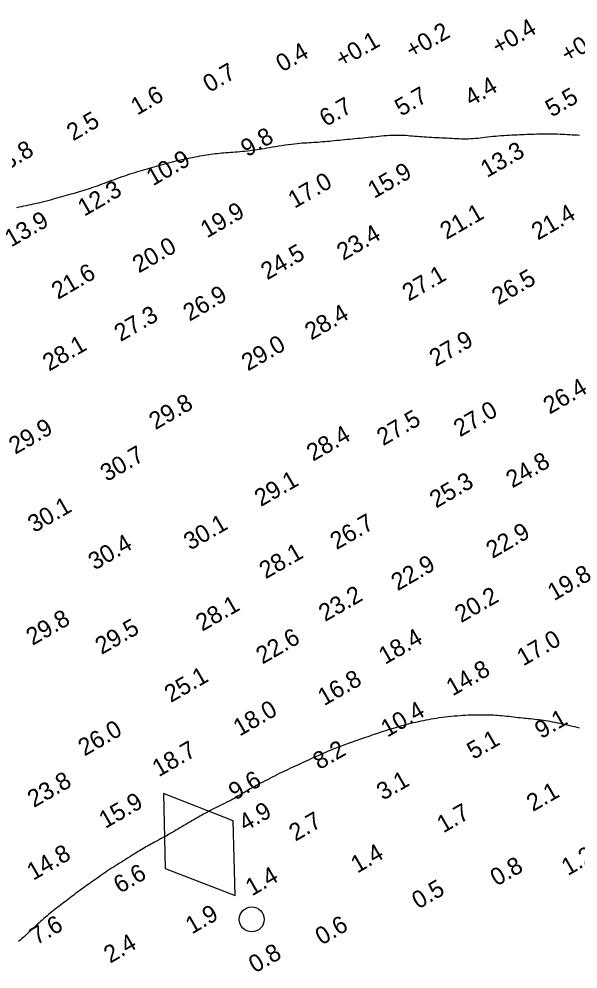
# Model space of a CAD drawing. Extents: x 3024098 to 3056816, y 418252 to 509144.
# Drawn here: x 3027600.4 to 3027761.7, y 427846.4 to 428120.8 of the extents above; entities that cross this region are included whole.
import ezdxf

# ---------------------------------------------------------------- set-up
doc = ezdxf.new("R2010")
doc.units = 0
for name, color, linetype in [('V-CHAN-CONT-EL10', 7, 'Continuous'), ('V-CHAN-NAID', 7, 'Continuous'), ('V-TOPO-SOUN-0911', 7, 'Continuous')]:
    doc.layers.add(name, color=color, linetype=linetype)

msp = doc.modelspace()

# ---------------------------------------------------------------- linework, layer by layer
at = {"layer": 'V-CHAN-CONT-EL10'}
for points in [[(3027599.77, 428066.31), (3027600.45, 428066.47), (3027601.12, 428066.63), (3027601.8, 428066.78), (3027602.49, 428066.93), (3027603.18, 428067.08), (3027603.88, 428067.23), (3027604.59, 428067.39), (3027605.31, 428067.55), (3027606.04, 428067.71), (3027606.79, 428067.89), (3027607.55, 428068.08), (3027608.31, 428068.27), (3027609.08, 428068.47), (3027609.84, 428068.67), (3027610.59, 428068.88), (3027611.33, 428069.08), (3027612.05, 428069.28), (3027612.75, 428069.47), (3027613.43, 428069.67), (3027614.09, 428069.85), (3027614.74, 428070.04), (3027615.38, 428070.23), (3027616.01, 428070.41), (3027616.63, 428070.6), (3027617.26, 428070.78), (3027617.88, 428070.96), (3027618.51, 428071.15), (3027619.14, 428071.34), (3027619.77, 428071.54), (3027620.4, 428071.74), (3027621.04, 428071.95), (3027621.69, 428072.16), (3027622.35, 428072.39), (3027623.01, 428072.62), (3027623.68, 428072.87), (3027624.36, 428073.12), (3027625.04, 428073.38), (3027625.74, 428073.65), (3027626.45, 428073.92), (3027627.16, 428074.19), (3027627.89, 428074.46), (3027628.63, 428074.73), (3027629.38, 428074.99), (3027630.13, 428075.26), (3027630.88, 428075.51), (3027631.64, 428075.77), (3027632.39, 428076.01), (3027633.13, 428076.25), (3027633.86, 428076.48), (3027634.58, 428076.7), (3027635.29, 428076.91), (3027635.98, 428077.11), (3027636.67, 428077.3), (3027637.36, 428077.49), (3027638.04, 428077.68), (3027638.71, 428077.87), (3027639.39, 428078.06), (3027640.06, 428078.25), (3027640.74, 428078.44), (3027641.43, 428078.63), (3027642.12, 428078.82), (3027642.82, 428079.02), (3027643.53, 428079.21), (3027644.26, 428079.4), (3027645.01, 428079.59), (3027645.77, 428079.78), (3027646.55, 428079.96), (3027647.33, 428080.15), (3027648.12, 428080.32), (3027648.9, 428080.49), (3027649.68, 428080.66), (3027650.44, 428080.81), (3027651.17, 428080.96), (3027651.88, 428081.1), (3027652.57, 428081.22), (3027653.24, 428081.34), (3027653.89, 428081.45), (3027654.52, 428081.55), (3027655.14, 428081.65), (3027655.76, 428081.73), (3027656.36, 428081.81), (3027656.97, 428081.88), (3027657.58, 428081.95), (3027658.19, 428082.01), (3027658.8, 428082.07), (3027659.42, 428082.12), (3027660.06, 428082.17), (3027660.7, 428082.23), (3027661.36, 428082.28), (3027662.04, 428082.33), (3027662.73, 428082.38), (3027663.44, 428082.43), (3027664.14, 428082.49), (3027664.85, 428082.55), (3027665.56, 428082.62), (3027666.26, 428082.69), (3027666.95, 428082.77), (3027667.63, 428082.85), (3027668.3, 428082.95), (3027668.97, 428083.05), (3027669.65, 428083.16), (3027670.35, 428083.28), (3027671.08, 428083.4), (3027671.84, 428083.53), (3027672.64, 428083.67), (3027673.5, 428083.82), (3027674.39, 428083.97), (3027675.31, 428084.12), (3027676.24, 428084.27), (3027677.17, 428084.41), (3027678.08, 428084.54), (3027678.97, 428084.66), (3027679.82, 428084.76), (3027680.62, 428084.84), (3027681.37, 428084.91), (3027682.08, 428084.97), (3027682.77, 428085.01), (3027683.43, 428085.05), (3027684.07, 428085.08), (3027684.7, 428085.12), (3027685.33, 428085.15), (3027685.97, 428085.19), (3027686.61, 428085.24), (3027687.26, 428085.29), (3027687.92, 428085.34), (3027688.58, 428085.4), (3027689.26, 428085.46), (3027689.95, 428085.53), (3027690.65, 428085.59), (3027691.36, 428085.66), (3027692.08, 428085.73), (3027692.82, 428085.8), (3027693.56, 428085.87), (3027694.3, 428085.95), (3027695.05, 428086.02), (3027695.81, 428086.09), (3027696.56, 428086.17), (3027697.31, 428086.24), (3027698.06, 428086.32), (3027698.81, 428086.39), (3027699.57, 428086.47), (3027700.32, 428086.54), (3027701.08, 428086.62), (3027701.85, 428086.69), (3027702.62, 428086.77), (3027703.39, 428086.85), (3027704.17, 428086.93), (3027704.94, 428087.01), (3027705.71, 428087.08), (3027706.48, 428087.14), (3027707.23, 428087.19), (3027707.96, 428087.23), (3027708.68, 428087.25), (3027709.37, 428087.26), (3027710.04, 428087.26), (3027710.7, 428087.24), (3027711.35, 428087.21), (3027711.99, 428087.17), (3027712.63, 428087.12), (3027713.27, 428087.07), (3027713.92, 428087.02), (3027714.57, 428086.97), (3027715.24, 428086.91), (3027715.92, 428086.86), (3027716.6, 428086.8), (3027717.3, 428086.75), (3027718, 428086.7), (3027718.72, 428086.66), (3027719.44, 428086.61), (3027720.17, 428086.57), (3027720.91, 428086.54), (3027721.65, 428086.5), (3027722.39, 428086.47), (3027723.13, 428086.43), (3027723.86, 428086.4), (3027724.59, 428086.36), (3027725.31, 428086.33), (3027726.02, 428086.29), (3027726.71, 428086.26), (3027727.4, 428086.22), (3027728.08, 428086.2), (3027728.75, 428086.18), (3027729.42, 428086.17), (3027730.09, 428086.18), (3027730.75, 428086.21), (3027731.41, 428086.25), (3027732.07, 428086.31), (3027732.74, 428086.38), (3027733.42, 428086.46), (3027734.11, 428086.55), (3027734.82, 428086.64), (3027735.54, 428086.73), (3027736.29, 428086.82), (3027737.06, 428086.9), (3027737.85, 428086.97), (3027738.65, 428087.03), (3027739.45, 428087.09), (3027740.26, 428087.15), (3027741.06, 428087.2), (3027741.85, 428087.24), (3027742.61, 428087.28), (3027743.35, 428087.32), (3027744.07, 428087.35), (3027744.78, 428087.39), (3027745.47, 428087.42), (3027746.17, 428087.45), (3027746.86, 428087.48), (3027747.56, 428087.5), (3027748.28, 428087.53), (3027749.01, 428087.55), (3027749.76, 428087.58), (3027750.52, 428087.6), (3027751.29, 428087.61), (3027752.05, 428087.62), (3027752.82, 428087.63), (3027753.58, 428087.62), (3027754.33, 428087.61), (3027755.06, 428087.59), (3027755.78, 428087.57), (3027756.49, 428087.53), (3027757.19, 428087.5), (3027757.89, 428087.46), (3027758.59, 428087.42), (3027759.29, 428087.38), (3027759.99, 428087.34), (3027760.7, 428087.31), (3027761.41, 428087.28), (3027762.12, 428087.25)], [(3027762.09, 427915.94), (3027761.42, 427916.12), (3027760.74, 427916.29), (3027760.05, 427916.46), (3027759.35, 427916.63), (3027758.64, 427916.8), (3027757.92, 427916.96), (3027757.19, 427917.12), (3027756.47, 427917.28), (3027755.75, 427917.43), (3027755.04, 427917.57), (3027754.34, 427917.7), (3027753.65, 427917.82), (3027752.98, 427917.94), (3027752.33, 427918.04), (3027751.68, 427918.14), (3027751.04, 427918.23), (3027750.42, 427918.32), (3027749.81, 427918.39), (3027749.2, 427918.47), (3027748.6, 427918.53), (3027748, 427918.59), (3027747.41, 427918.65), (3027746.82, 427918.71), (3027746.22, 427918.77), (3027745.61, 427918.83), (3027744.99, 427918.89), (3027744.36, 427918.96), (3027743.71, 427919.04), (3027743.05, 427919.11), (3027742.39, 427919.2), (3027741.71, 427919.28), (3027741.04, 427919.35), (3027740.38, 427919.43), (3027739.72, 427919.5), (3027739.07, 427919.55), (3027738.44, 427919.6), (3027737.82, 427919.64), (3027737.21, 427919.68), (3027736.62, 427919.7), (3027736.03, 427919.72), (3027735.45, 427919.73), (3027734.88, 427919.74), (3027734.3, 427919.74), (3027733.73, 427919.74), (3027733.15, 427919.74), (3027732.57, 427919.73), (3027731.96, 427919.72), (3027731.33, 427919.7), (3027730.67, 427919.68), (3027729.98, 427919.65), (3027729.25, 427919.61), (3027728.47, 427919.56), (3027727.65, 427919.51), (3027726.8, 427919.44), (3027725.94, 427919.37), (3027725.06, 427919.29), (3027724.18, 427919.2), (3027723.31, 427919.1), (3027722.46, 427919), (3027721.64, 427918.89), (3027720.84, 427918.77), (3027720.06, 427918.65), (3027719.3, 427918.52), (3027718.55, 427918.38), (3027717.81, 427918.24), (3027717.08, 427918.09), (3027716.35, 427917.94), (3027715.62, 427917.78), (3027714.89, 427917.61), (3027714.16, 427917.44), (3027713.43, 427917.27), (3027712.7, 427917.08), (3027711.97, 427916.89), (3027711.24, 427916.7), (3027710.5, 427916.5), (3027709.77, 427916.29), (3027709.04, 427916.08), (3027708.31, 427915.86), (3027707.58, 427915.64), (3027706.87, 427915.42), (3027706.16, 427915.19), (3027705.46, 427914.97), (3027704.78, 427914.75), (3027704.12, 427914.53), (3027703.47, 427914.31), (3027702.83, 427914.09), (3027702.2, 427913.88), (3027701.59, 427913.66), (3027700.99, 427913.45), (3027700.4, 427913.24), (3027699.81, 427913.04), (3027699.23, 427912.83), (3027698.67, 427912.63), (3027698.1, 427912.43), (3027697.55, 427912.24), (3027697, 427912.05), (3027696.46, 427911.86), (3027695.93, 427911.67), (3027695.4, 427911.48), (3027694.89, 427911.3), (3027694.37, 427911.12), (3027693.86, 427910.94), (3027693.34, 427910.75), (3027692.82, 427910.56), (3027692.29, 427910.36), (3027691.75, 427910.16), (3027691.19, 427909.94), (3027690.62, 427909.71), (3027690.03, 427909.46), (3027689.42, 427909.21), (3027688.8, 427908.94), (3027688.17, 427908.66), (3027687.52, 427908.38), (3027686.86, 427908.08), (3027686.19, 427907.78), (3027685.51, 427907.47), (3027684.82, 427907.16), (3027684.12, 427906.84), (3027683.43, 427906.52), (3027682.74, 427906.2), (3027682.05, 427905.88), (3027681.36, 427905.57), (3027680.69, 427905.25), (3027680.03, 427904.95), (3027679.37, 427904.65), (3027678.72, 427904.35), (3027678.08, 427904.05), (3027677.44, 427903.74), (3027676.79, 427903.44), (3027676.13, 427903.12), (3027675.47, 427902.8), (3027674.8, 427902.46), (3027674.12, 427902.12), (3027673.44, 427901.77), (3027672.75, 427901.42), (3027672.07, 427901.06), (3027671.39, 427900.71), (3027670.73, 427900.35), (3027670.08, 427900.01), (3027669.45, 427899.67), (3027668.83, 427899.34), (3027668.24, 427899.02), (3027667.66, 427898.7), (3027667.1, 427898.39), (3027666.56, 427898.09), (3027666.04, 427897.79), (3027665.53, 427897.5), (3027665.04, 427897.21), (3027664.57, 427896.92), (3027664.1, 427896.63), (3027663.62, 427896.35), (3027663.14, 427896.06), (3027662.64, 427895.77), (3027662.11, 427895.47), (3027661.56, 427895.17), (3027660.97, 427894.86), (3027660.35, 427894.54), (3027659.71, 427894.23), (3027659.06, 427893.9), (3027658.41, 427893.58), (3027657.75, 427893.26), (3027657.11, 427892.94), (3027656.48, 427892.63), (3027655.88, 427892.32), (3027655.3, 427892.02), (3027654.73, 427891.72), (3027654.18, 427891.42), (3027653.63, 427891.11), (3027653.09, 427890.81), (3027652.54, 427890.5), (3027651.99, 427890.18), (3027651.42, 427889.85), (3027650.84, 427889.51), (3027650.26, 427889.17), (3027649.67, 427888.83), (3027649.08, 427888.48), (3027648.5, 427888.14), (3027647.91, 427887.79), (3027647.33, 427887.45), (3027646.77, 427887.11), (3027646.21, 427886.78), (3027645.65, 427886.46), (3027645.1, 427886.14), (3027644.56, 427885.82), (3027644, 427885.5), (3027643.45, 427885.18), (3027642.89, 427884.87), (3027642.32, 427884.55), (3027641.75, 427884.24), (3027641.18, 427883.93), (3027640.61, 427883.62), (3027640.04, 427883.32), (3027639.49, 427883.02), (3027638.96, 427882.73), (3027638.44, 427882.44), (3027637.95, 427882.17), (3027637.47, 427881.89), (3027637, 427881.62), (3027636.54, 427881.35), (3027636.07, 427881.08), (3027635.6, 427880.79), (3027635.11, 427880.5), (3027634.6, 427880.18), (3027634.06, 427879.85), (3027633.5, 427879.51), (3027632.92, 427879.15), (3027632.32, 427878.78), (3027631.72, 427878.41), (3027631.12, 427878.03), (3027630.52, 427877.66), (3027629.92, 427877.28), (3027629.34, 427876.92), (3027628.77, 427876.56), (3027628.2, 427876.2), (3027627.64, 427875.84), (3027627.08, 427875.48), (3027626.52, 427875.12), (3027625.95, 427874.74), (3027625.39, 427874.36), (3027624.81, 427873.97), (3027624.24, 427873.57), (3027623.66, 427873.16), (3027623.09, 427872.75), (3027622.52, 427872.35), (3027621.96, 427871.95), (3027621.41, 427871.55), (3027620.88, 427871.17), (3027620.37, 427870.81), (3027619.87, 427870.45), (3027619.39, 427870.11), (3027618.92, 427869.77), (3027618.45, 427869.44), (3027617.99, 427869.11), (3027617.54, 427868.78), (3027617.08, 427868.44), (3027616.61, 427868.1), (3027616.15, 427867.74), (3027615.68, 427867.39), (3027615.21, 427867.03), (3027614.73, 427866.66), (3027614.25, 427866.29), (3027613.77, 427865.92), (3027613.29, 427865.55), (3027612.8, 427865.17), (3027612.31, 427864.8), (3027611.83, 427864.42), (3027611.34, 427864.04), (3027610.85, 427863.66), (3027610.37, 427863.28), (3027609.88, 427862.9), (3027609.4, 427862.51), (3027608.93, 427862.12), (3027608.46, 427861.72), (3027608, 427861.33), (3027607.53, 427860.93), (3027607.08, 427860.52), (3027606.62, 427860.12), (3027606.18, 427859.71), (3027605.73, 427859.31), (3027605.29, 427858.9), (3027604.86, 427858.49), (3027604.43, 427858.08), (3027604, 427857.68), (3027603.57, 427857.28), (3027603.15, 427856.89), (3027602.74, 427856.5), (3027602.33, 427856.13), (3027601.92, 427855.77), (3027601.51, 427855.42), (3027601.1, 427855.07), (3027600.69, 427854.72), (3027600.26, 427854.35)]]:
    msp.add_lwpolyline(points, dxfattribs=at)
at = {"layer": 'V-CHAN-NAID'}
msp.add_lwpolyline([(3027662.7, 427867.59), (3027662.21, 427889.22), (3027642.05, 427897.08), (3027642.55, 427875.45)], close=True, dxfattribs=at)
msp.add_circle((3027667.52, 427860.71), 3.6, dxfattribs=at)

# ---------------------------------------------------------------- texts
at = {"layer": 'V-TOPO-SOUN-0911'}
for s, p in [('+0.2 ', (3027713.75, 428109.18)), ('+0.4 ', (3027738.65, 428110.26)), ('+0.3 ', (3027758.59, 428107.99)), ('+0.1 ', (3027693.49, 428106.57)), ('0.4', (3027676.34, 428105.31)), ('0.7', (3027655.31, 428099.4)), ('4.4', (3027730.81, 428095.44)), ('1.6', (3027634.48, 428092.85)), ('5.7', (3027710.66, 428092.55)), ('5.5', (3027754.09, 428092.29)), ('6.7', (3027688.91, 428089.53)), ('2.5', (3027615.97, 428085.4)), ('9.8', (3027666.21, 428080.8)), ('3.8', (3027597.01, 428077.03)), ('10.9 ', (3027638.98, 428072.4)), ('13.3 ', (3027735.4, 428074.82)), ('15.9 ', (3027702.85, 428068.79)), ('17.0 ', (3027679.87, 428065.93)), ('12.3 ', (3027619.19, 428063.64)), ('19.9 ', (3027654.59, 428057.37)), ('21.1 ', (3027723.7, 428056.93)), ('21.4 ', (3027750.1, 428056.75)), ('13.9 ', (3027598.1, 428054.75)), ('23.4 ', (3027693.9, 428050.87)), ('20.0 ', (3027634.96, 428047.26)), ('24.5 ', (3027672, 428045.26)), ('21.6 ', (3027611.61, 428039.63)), ('27.1 ', (3027712.81, 428039.11)), ('26.5 ', (3027738.64, 428038.01)), ('26.9 ', (3027649.57, 428033.32)), ('27.3 ', (3027629.69, 428027.45)), ('28.4 ', (3027684.68, 428027.88)), ('27.9 ', (3027720.6, 428020.23)), ('28.1 ', (3027609.04, 428018.9)), ('29.0 ', (3027666.42, 428018.95)), ('26.4 ', (3027753.48, 428006.49)), ('29.8 ', (3027639.73, 428001.99)), ('27.0 ', (3027727.61, 427999.92)), ('27.5 ', (3027705.44, 427997.36)), ('29.9 ', (3027599.28, 427994.87)), ('28.4 ', (3027685.2, 427992.87)), ('30.7 ', (3027625.69, 427987)), ('24.8 ', (3027742.72, 427985.16)), ('29.1 ', (3027670.16, 427979.79)), ('25.3 ', (3027720.7, 427979.35)), ('30.1 ', (3027604.74, 427972.25)), ('30.1 ', (3027649.75, 427967.2)), ('26.7 ', (3027691.99, 427967.34)), ('22.9 ', (3027736.97, 427964.79)), ('30.4 ', (3027622.21, 427961.44)), ('28.1 ', (3027671.54, 427958.9)), ('22.9 ', (3027709.61, 427955.47)), ('19.8 ', (3027754.72, 427952.58)), ('23.2 ', (3027688.68, 427946.58)), ('20.2 ', (3027727.95, 427946.25)), ('28.1 ', (3027653.23, 427943.77)), ('29.8 ', (3027604.26, 427939.69)), ('29.5 ', (3027624.2, 427937.06)), ('22.6 ', (3027670.6, 427934.28)), ('18.4 ', (3027706, 427934.21)), ('17.0 ', (3027745.88, 427933.75)), ('14.8 ', (3027725.49, 427925.09)), ('25.1 ', (3027644.17, 427923.2)), ('16.8 ', (3027688.42, 427922.27)), ('18.0 ', (3027664.03, 427913.47)), ('10.4 ', (3027706.63, 427913.18)), ('9.1', (3027751.03, 427912.74)), ('26.0 ', (3027619.27, 427907.73)), ('18.7 ', (3027640.68, 427901.73)), ('5.1', (3027731.48, 427906.77)), ('8.2', (3027687.04, 427903.8)), ('23.8 ', (3027604.66, 427892.87)), ('9.6', (3027662.69, 427894.98)), ('3.1', (3027705.39, 427894.96)), ('2.1', (3027748.67, 427891.71)), ('15.9 ', (3027625.29, 427886.83)), ('4.9', (3027665.63, 427886)), ('1.7', (3027722.8, 427885.53)), ('2.7', (3027680.12, 427883.13)), ('14.8 ', (3027604.49, 427871.84)), ('1.4', (3027697.96, 427873.91)), ('1.2', (3027758.73, 427873.19)), ('6.6', (3027629.49, 427868.08)), ('0.8', (3027738.19, 427870.17)), ('1.4', (3027667.58, 427867.32)), ('0.5', (3027715.57, 427863.55)), ('1.9', (3027650.26, 427856.33)), ('7.6', (3027605.44, 427853.22)), ('0.6', (3027687.69, 427853.15)), ('2.4', (3027626.67, 427847.9)), ('0.8', (3027668.47, 427845.07))]:
    msp.add_text(s, height=5, rotation=30, dxfattribs=at).set_placement(p)

doc.saveas('drawing.dxf')
